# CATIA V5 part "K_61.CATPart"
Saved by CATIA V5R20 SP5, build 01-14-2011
Part number: 61
Bounding box of the stored display mesh (mm): x 0 to 50, y -150 to 150, z -20 to 20
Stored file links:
  G:\Khaled_CFAO_2011\ST2M\ST2M_GR1\lpierredon\Khaled\CAD_thinkMOTION\K_61.CATPart
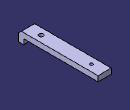
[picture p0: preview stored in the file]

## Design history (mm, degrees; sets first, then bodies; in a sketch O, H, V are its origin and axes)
Body1 (main body)
  Sketch1 on yz-plane, origin (0, 0, 0), H (0, 1, 0), V (0, 0, 1)
    line L1 (-130, 0) -> (150, 0)
    line L2 (150, 0) -> (150, 20)
    line L3 (150, 20) -> (-150, 20)
    line L4 (-150, 20) -> (-150, -20)
    line L5 (-150, -20) -> (-130, -20)
    line L6 (-130, -20) -> (-130, 0)
    distance L6 L2 = 280
    length L5 = 20
    length L2 = 20
    length L4 = 40
    horizontal: L1 H, L3 H, L5 H
    vertical: L2 V, L4 V, L6 V
    symmetry: L4 L2 V, L3 L5 H
  Pad1: profile Sketch1, direction (1, 0, 0), length 50
  Chamfer1: length 10, angle 45, on edge [face of Pad1 from Sketch1.L4 | face of Pad1 from Sketch1.L3]
  Chamfer2: length 2, angle 45, on edge [face of Pad1 from Sketch1.L5 | face of Pad1 from Sketch1.L4]
  Chamfer3: length 2, angle 45, on edge [face of Pad1 from Sketch1.L6 | face of Pad1 from Sketch1.L5]
  Sketch2 on face of Pad1 from Sketch1.L3, origin (27.8536, -86.943, 20), H (1, 0, 0), V (0, 1, 0)
    point P1 (-2.8536, -3.057)
    reference projected line E1 (22.1464, 236.943) -> (22.1464, -63.057) from edge [face of Pad1 from Sketch1.L3 | end face of Pad1]
    reference projected line E2 (-27.8536, 236.943) -> (-27.8536, -63.057) from edge [start face of Pad1 | face of Pad1 from Sketch1.L3]
    reference projected line E3 (-27.8536, 236.943) -> (22.1464, 236.943) from edge [face of Pad1 from Sketch1.L3 | face of Pad1 from Sketch1.L2]
    distance P1 E3 = 240
    equidistance: E1 E2 P1
  Hole1: placed by Sketch2, at (25, -90, 20) direction (0, 0, -1), diameter 16, through (limit type 6)
  Sketch3 on face of Pad1 from Sketch1.L3, origin (31.22, 98.4118, 20), H (1, 0, 0), V (0, 1, 0)
    point P1 (-6.22, 1.5882)
    reference projected line E1 (-31.22, 51.5882) -> (-31.22, -248.4118) from edge [start face of Pad1 | face of Pad1 from Sketch1.L3]
    reference projected line E2 (18.78, 51.5882) -> (18.78, -248.4118) from edge [face of Pad1 from Sketch1.L3 | end face of Pad1]
    reference projected line E3 (-31.22, 51.5882) -> (18.78, 51.5882) from edge [face of Pad1 from Sketch1.L3 | face of Pad1 from Sketch1.L2]
    distance P1 E3 = 50
    equidistance: E1 E2 P1
  Hole2: placed by Sketch3, at (25, 100, 20) direction (0, 0, -1), diameter 11, through (limit type 6)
